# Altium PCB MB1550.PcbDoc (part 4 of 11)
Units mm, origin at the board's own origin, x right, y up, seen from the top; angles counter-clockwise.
Board outline 154.81 x 170.69 mm, 6 copper layers (Top Layer, Signal Layer 1, Signal Layer 2, Signal Layer 3, Signal Layer 4, Bottom Layer), stack 1.49 mm thick; 810 components, 633 nets, 2973 pads, 2150 vias.
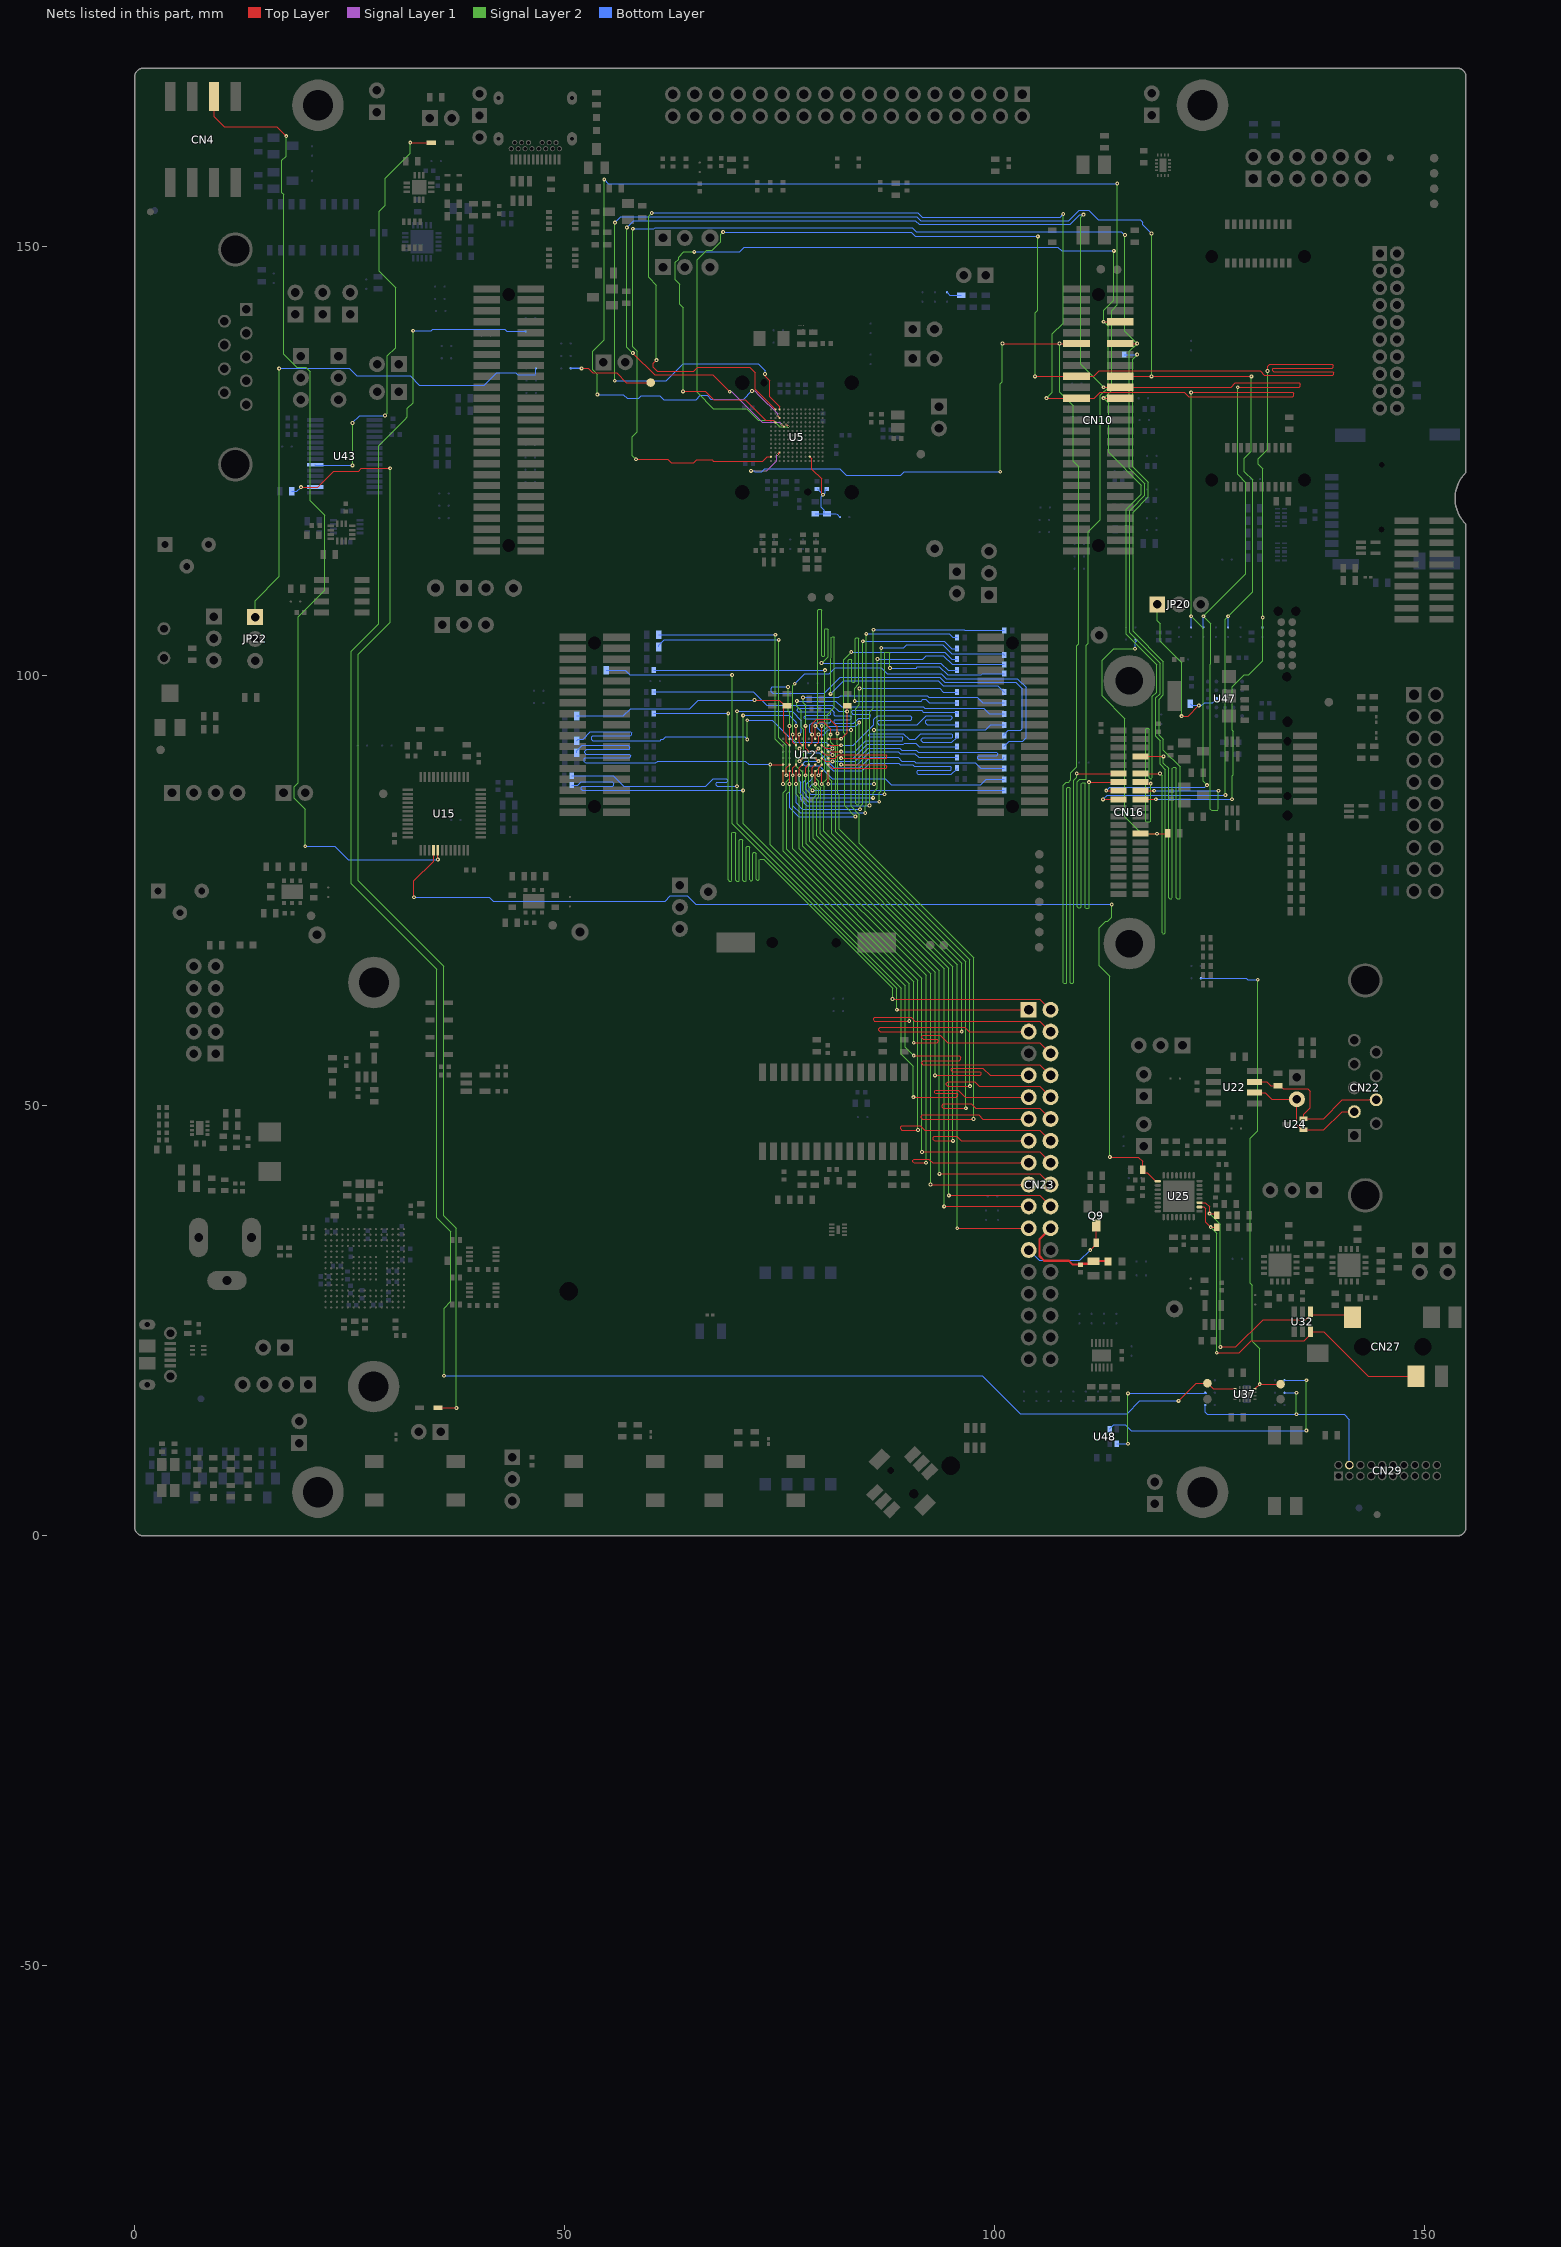
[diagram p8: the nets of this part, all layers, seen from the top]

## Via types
v1: diameter 0.45, hole 0.2, Top Layer to Bottom Layer, tented both sides, 1777 vias
v2: diameter 0.25, hole 0.1, Top Layer to Signal Layer 1, tented top, 344 vias
v3: diameter 0.25, hole 0.1, Signal Layer 1 to Signal Layer 2, 29 vias

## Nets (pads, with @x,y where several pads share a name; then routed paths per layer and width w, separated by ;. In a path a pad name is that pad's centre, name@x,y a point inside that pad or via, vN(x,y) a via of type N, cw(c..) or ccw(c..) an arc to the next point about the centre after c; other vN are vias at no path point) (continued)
A7: R221.2 U12.D4 | length 29.6
  Top Layer w0.1: v1(77.3,91.546) U12.D4@77.65,91.196
  Bottom Layer w0.1: v1(77.3,91.546) 77.771,91.075 79.625,91.075 80.375,90.325 80.375,89.85 81.229,88.996 84.611,88.996 85.49,89.875 88.853,89.875 89.033,89.694 90.456,89.694 90.65,89.5 94.825,89.5 94.95,89.375 94.95,89.075 94.9,89.025 91.075,89.025 90.975,88.925 90.975,88.675 91.075,88.575 94.975,88.575 95.625,89.225 R221.2@95.625,89.275
A8: R219.2 U12.H2 | length 26.9
  Top Layer w0.1: U12.H2@80.65,89.696 81.096,89.25 87.35,89.25 87.45,89.35 87.45,89.525 87.279,89.696 v1(82.146,89.696)
  Bottom Layer w0.1: v1(82.146,89.696) 83.996,89.696 85.475,91.175 88.8,91.175 89.011,90.964 90.711,90.964 91.15,90.525 R219.2@95.625,90.525
A9: R215.2 U12.H3 | length 26.9
  Top Layer w0.1: U12.H3@80.65,90.446 81.446,90.446 81.825,90.825 87.375,90.825 87.45,90.75 87.45,90.517 87.379,90.446 v1(82.146,90.446)
  Bottom Layer w0.1: v1(82.146,90.446) 83.546,90.446 85.175,92.075 89.4,92.075 89.523,92.198 90.827,92.198 91.25,91.775 R215.2@95.625,91.775
A10: R209.2 U12.H4 | length 32.9
  Top Layer w0.1: U12.H4@80.65,91.196 v1(82.146,91.196)
  Bottom Layer w0.1: v1(82.146,91.196) 83.706,91.196 85.002,92.492 89.227,92.492 89.325,92.59 89.325,92.85 89.25,92.925 85.5,92.925 85.375,93.05 85.375,93.185 85.498,93.308 89.392,93.308 90.049,92.651 90.775,92.651 91.432,93.308 94.992,93.308 95.1,93.2 95.1,92.9 95.025,92.825 91.625,92.825 91.45,92.65 91.45,92.475 91.625,92.3 95.025,92.3 95.625,92.9 R209.2@95.625,93.05
A11: R203.2 U12.H5 | length 32.6
  Top Layer w0.1: U12.H5@80.65,91.946 v1(82.146,91.946)
  Bottom Layer w0.1: v1(82.146,91.946) 83.546,91.946 85.95,94.35 85.95,94.95 86.4,95.4 90.175,95.4 90.35,95.225 90.35,94.975 90.225,94.85 86.55,94.85 86.4,94.7 86.4,94.475 86.525,94.35 91.025,94.35 92.066,95.391 94.884,95.391 95.05,95.225 95.05,95.063 94.912,94.925 92.1,94.925 91.975,94.8 91.975,94.517 92.142,94.35 R203.2@95.625,94.35
A12: R217.2 U12.G3 | length 27.5
  Top Layer w0.1: U12.G3@79.9,90.446 80.275,90.071 v1(81.146,90.071)
  Bottom Layer w0.1: v1(81.146,90.071) 83.782,90.071 85.302,91.592 88.973,91.592 89.183,91.381 90.883,91.381 91.115,91.15 100.203,91.15 100.35,91.003 100.35,90.825 100.25,90.725 98.15,90.725 98.025,90.6 98.025,90.4 98.1,90.325 100.925,90.325 R217.2@101.125,90.525
A13: R222.2 U12.G4 | length 26.9
  Top Layer w0.1: U12.G4@79.9,91.196 80.275,90.821 v1(81.146,90.821)
  Bottom Layer w0.1: v1(81.146,90.821) 80.142,91.825 80,91.825 79.878,91.703 79.878,91.297 80.75,90.425 80.75,89.925 81.375,89.3 84.325,89.3 85.55,90.525 88.792,90.525 89.206,90.111 90.628,90.111 90.815,89.925 97.716,89.925 98.391,89.25 R222.2@101.125,89.25
A14: R226.2 U12.F3 | length 27.1
  Top Layer w0.1: U12.F3@79.15,90.446 v1(79.5,90.096)
  Bottom Layer w0.1: v1(79.5,90.096) 77.971,90.096 77.8,89.925 77.8,89.7 77.95,89.55 79.625,89.55 81.14,88.035 87.265,88.035 87.975,87.325 98.375,87.325 99.025,87.975 R226.2@101.125,87.975
A15: R229.2 U12.F4 | length 28.3
  Top Layer w0.1: U12.F4@79.15,91.196 v1(79.5,91.546)
  Signal Layer 2 w0.09: v1(78.825,86.7) 78.4,87.125 78.4,90.446 v1(79.5,91.546)
  Bottom Layer w0.1: v1(78.825,86.7) R229.2@101.125,86.7
A16: R196.1 U12.E4 | length 30.4
  Top Layer w0.1: v1(78.025,94.2) 78.025,91.571 U12.E4@78.4,91.196
  Signal Layer 2 w0.09: v1(77.725,97.5) 77.725,96.9 78.025,96.6 v1(78.025,94.2)
  Bottom Layer w0.1: v1(77.725,97.5) 81.879,97.5 82.075,97.695 92.167,97.695 92.362,97.5 97.975,97.5 98.6,96.875 R196.1@101.125,96.875
A17: R199.1 U12.D3 | length 32.8
  Top Layer w0.1: v1(77.3,90.096) U12.D3@77.65,90.446
  Signal Layer 2 w0.09: v1(77,97.083) 77,96.475 77.525,95.95 77.525,94.025 77.8,93.75 77.8,90.596 v1(77.3,90.096)
  Bottom Layer w0.1: v1(77,97.083) 81.542,97.083 82.2,96.425 91.692,96.425 91.892,96.225 98.729,96.225 99.354,95.6 R199.1@101.125,95.6
A18: R204.1 U12.H1 | length 28.5
  Top Layer w0.1: v1(80.65,87.45) U12.H1@80.65,88.946
  Signal Layer 2 w0.09: v1(85.975,87.45) v1(85.975,93.725)
  Bottom Layer w0.1: v1(80.65,87.45) v1(85.975,87.45) ; v1(85.975,93.725) 98.975,93.725 99.575,94.325 R204.1@101.125,94.325
A19: R189.1 U12.G2 | length 33.8
  Top Layer w0.1: v1(79.525,88.45) 79.525,89.321 U12.G2@79.9,89.696
  Signal Layer 2 w0.09: v1(79.525,88.45) 80.266,89.191 80.266,94.975 80.265,94.976 v1(80.265,100.675)
  Bottom Layer w0.1: R189.1@60.375,100.675 v1(80.265,100.675)
A20: R38.1 R191.2 U12.H6 | length 29
  Top Layer w0.1: U12.H6@80.65,92.696 v1(82.146,92.696) 82.85,93.4 v1(82.85,95.875) R38.1@82.85,96.525
  Bottom Layer w0.1: R191.2@60.375,98.15 71.95,98.15 73.5,96.6 81.125,96.6 81.85,95.875 v1(82.85,95.875)
ADC_DAC: R144.2 SB16.2 | length 1.8
  Bottom Layer w0.12: SB16.2@94.475,144.625 94.8,144.3 R144.2@96.1,144.3
ADF1_CCK0: SB115.2 TP36.1 U37.16 | length 57.8
  Top Layer w0.12: U37.16@130.275,17.1 v1(130.825,17.65) TP36.1@133.25,17.65
  Signal Layer 2 w0.12: v1(130.6,64.675) 130.6,47.1 129.72,46.22 129.72,29.405 129.975,29.15 129.975,22.625 130.825,21.775 v1(130.825,17.65)
  Bottom Layer w0.12: SB115.2@123.975,64.85 123.975,64.82 129.282,64.82 129.427,64.675 v1(130.6,64.675)
ADF1_CCK0_MEMS: SB134.2 U48.4 | length 31.8
  Signal Layer 2 w0.12: v1(136.245,12.245) v1(136.245,18.095)
  Bottom Layer w0.12: U48.4@113.367,12.388 113.367,12.444 113.854,12.93 115.195,12.93 115.88,12.245 v1(136.245,12.245) ; SB134.2@133.7,18.1 v1@136.25,18.1
ADF1_SDIN0: SB26.2 TP35.1 U37.5 | length 238.4
  Top Layer w0.12: v1(121.4,15.7) 123.45,17.75 TP35.1@124.75,17.75 125.4,17.1 U37.5@127.925,17.1
  Signal Layer 2 w0.12: v1(32.375,140.15) 32.375,131.768 31.72,131.113 31.72,130.12 31.475,129.875 28.395,126.795 28.395,106.07 25.2,102.875 25.2,75.85 35.15,65.9 35.15,36.975 36.755,35.37 36.755,27.28 35.975,26.5 v1(35.975,18.625)
  Bottom Layer w0.12: v1(32.375,140.15) 34.475,140.15 34.655,140.33 43.018,140.33 43.273,140.075 SB26.2@45.45,140.075 ; v1(35.975,18.625) 98.575,18.625 103.005,14.195 115.395,14.195 116.9,15.7 v1(121.4,15.7)
ADF1_SDIN0_MEMS: SB145.2 U48.1 | length 16.3
  Signal Layer 2 w0.12: v1(115.5,10.712) v1(115.5,16.575)
  Bottom Layer w0.12: U48.1@114.189,10.712 v1(115.5,10.712) ; v1(115.5,16.575) 124.65,16.575
AGND: C140.1 C141.1 C148.2 C149.2 SB76.2 U5.K2 | length 12.4
  Top Layer w0.08: U5.K2@78.5,125.5 78.75,125.25 78.75,124.05 79.875,122.925 79.875,121.25 v1(80.05,121.075)
  Bottom Layer w0.1: C149.2@79.125,118.875 C148.2@80.2,118.875 ; C141.1@79.35,121.75 79.375,121.75 v1(80.05,121.075) ; C140.1@80.475,121.75 80.3,121.575 80.3,121.325 v1(80.05,121.075) ; 81.675,118.8 81.6,118.875 C148.2@80.5,118.875 C148.2@80.2,118.875 ; v1(80.05,121.075) 79.825,120.85 79.825,119.625 80.2,119.25 C148.2@80.2,118.875
  Bottom Layer w0.12: 81.675,118.8 SB76.2@82,118.475
AOUTA: C84.2 CN27.6 U25.11 U32.4 | length 36.4
  Top Layer w0.12: U25.11@123.825,38.75 124.5,38.75 125,38.25 v1(125,37.475) 125.625,37.475 C84.2@125.8,37.3 ; v1(126.25,21.975) 128.05,21.975 131.225,25.15 136.2,25.15 136.75,25.7 U32.4@136.75,25.725 ; U32.4@136.75,26.05 U32.4@136.75,25.725 ; CN27.6@141.6,25.45 141.325,25.725 U32.4@136.75,25.725
  Signal Layer 2 w0.12: v1(125,37.475) 126.25,36.225 v1(126.25,21.975)
AOUTB: C86.2 CN27.4 U25.10 U32.3 | length 45.3
  Top Layer w0.12: U25.10@123.825,38.25 124.325,38.25 124.55,38.025 124.55,36.475 v1(125.125,35.9) C86.2@125.8,35.9 ; v1(125.825,21.3) 128.425,21.3 129.825,22.7 136,22.7 136.75,23.45 U32.3@136.75,23.75 138.275,23.75 143.475,18.55 CN27.4@149,18.55
  Signal Layer 2 w0.12: v1(125.125,35.9) 125.825,35.2 v1(125.825,21.3)
BL_CTRL: CN23.23 Q9.3 R104.1 | length 11.3
  Top Layer w0.12: v1(111.125,33.225) 111.8,33.9 R104.1@111.8,34.1 Q9.3@111.8,36.1
  Bottom Layer w0.12: CN23.23@103.96,33.24 105.175,32.025 109.925,32.025 v1(111.125,33.225)
BLGND: C92.1 C93.1 CN23.22 L3.2 | length 12.3
  Top Layer w0.25: CN23.22@106.5,35.78 105.225,34.505 105.225,32.55 105.775,32 108.625,32 109.075,31.55 C93.1@110,31.55 110.1,31.65 111.2,31.65 C92.1@111.5,31.95 113.15,31.95 L3.2@113.2,31.9
Bootloader_BOOT0: D1.1 U43.20 | length 50.5
  Top Layer w0.12: v1(32.04,162.025) D1.1@34.48,162.025
  Signal Layer 2 w0.12: v1(25.325,124.49) v1(25.325,129.425) ; v1(29.1,130.286) 29.375,130.561 29.375,137.222 30.338,138.185 30.338,145.144 28.425,147.057 28.425,154.05 29.125,154.75 29.125,157.9 32.04,160.815 v1(32.04,162.025)
  Bottom Layer w0.12: U43.20@20.976,124.561 20.976,124.495 20.981,124.49 v1(25.325,124.49) ; v1(25.325,129.425) 25.3,129.425 26.161,130.286 v1(29.1,130.286)
BOOTLOADER_RST: D9.2 R161.2 U43.16 | length 131.9
  Top Layer w0.12: v1(19.336,121.961) 21.286,121.961 23.151,123.825 26.025,123.825 26.35,124.15 v1(29.7,124.15) ; D9.2@35.27,14.9 35.5,14.9 35.525,14.875 v1(37.4,14.875)
  Signal Layer 2 w0.12: v1(29.7,124.15) 29.7,106.225 26,102.525 26,76.175 35.95,66.225 35.95,37.225 37.4,35.775 v1(37.4,14.875)
  Bottom Layer w0.12: R161.2@18.25,121.475 18.85,121.475 v1(19.336,121.961) U43.16@20.976,121.961
CAMERA_PLUG: CN16.15 R52.1 SB103.2 | length 32.6
  Top Layer w0.12: CN16.15@116.95,81.655 v1(118.87,81.655) 120.055,81.655 R52.1@120.125,81.725
  Signal Layer 2 w0.12: v1(116.325,103.163) 113.838,103.163 112.495,101.82 112.495,97.705 115.15,95.05 115.15,83.625 117.12,81.655 v1(118.87,81.655)
  Bottom Layer w0.12: v1(116.325,103.163) 116.325,103.925 116.625,104.225
CANH: CN22.7 R81.1 U22.7 U24.2 | length 19.8
  Top Layer w0.12: U24.2@135.925,48.525 138.25,48.525 140.44,50.715 CN22.7@144.37,50.715
  Top Layer w0.13: U22.7@130.225,52.81 131.665,52.81 132.1,52.375 R81.1@132.95,52.375 133.175,52.375 133.55,52 136.4,52 136.7,51.7 136.7,49.785 135.925,49.01 U24.2@135.925,48.525
CANL: CN22.2 JP28.2 U22.6 U24.1 | length 16
  Top Layer w0.12: U24.1@135.925,47.225 138.3,47.225 140.405,49.33 CN22.2@141.83,49.33
  Top Layer w0.13: U22.6@130.225,51.54 131.485,51.54 132.25,50.775 JP28.2@135.15,50.775 135.15,47.8 135.725,47.225 U24.1@135.925,47.225
CCK0_EXT: CN29.4 SB144.2 SB147.2 | length 27.1
  Signal Layer 2 w0.12: v1(135.1,14.15) v1(135.1,16.65)
  Bottom Layer w0.12: SB147.2@124.5,15.225 124.5,14.4 124.75,14.15 v1(135.1,14.15) 140.631,14.15 141.255,13.526 CN29.4@141.255,8.235 ; SB144.2@133.7,16.65 v1(135.1,16.65)
CODEC_RSTN: R85.2 U15.28 U25.25 | length 126.6
  Top Layer w0.12: v1(32.475,74.275) 32.475,76.2 34.748,78.473 U15.28@34.748,79.75 ; v1(113.4,44.05) 116.7,44.05 117.2,43.55 R85.2@117.2,42.6 117.2,42.225 117.775,42.225 118.75,41.25 U25.25@118.975,41.25
  Signal Layer 2 w0.12: v1(113.4,44.05) 113.4,65.1 112.175,66.325 112.175,70.733 112.916,71.474 113.141,71.474 113.625,71.958 v1(113.625,73.425)
  Bottom Layer w0.12: v1(32.475,74.275) 41.2,74.275 41.675,73.8 61.675,73.8 62.3,74.425 64.25,74.425 65.25,73.425 v1(113.625,73.425)
COMP2_INP: JP22.1 SB40.2 | length 62.1
  Signal Layer 2 w0.12: JP22.1@14,106.84 14,108.775 16.795,111.57 v1(16.795,135.765)
  Bottom Layer w0.12: v1(16.795,135.765) 24.96,135.765 25.81,134.915 32.035,134.915 33.115,133.835 40.635,133.835 42.075,135.275 44.333,135.275 44.558,135.05 46.55,135.05 46.65,135.15 SB40.2@46.65,135.775
COMP2_OUT: SB39.2 TP9.1 | length 10
  Top Layer w0.102: v1(51.975,135.775) 52.725,135.775 53.25,135.25 56.05,135.25
  Top Layer w0.12: 56.05,135.25 57.175,134.125 TP9.1@60,134.125
  Bottom Layer w0.2: SB39.2@50.7,135.775 v1(51.975,135.775)
CSn: JP20.1 R195.1 U47.C2 | length 20.1
  Top Layer w0.12: v1(121.75,95.325) 122.5,95.325 v1(123.75,96.575)
  Signal Layer 2 w0.12: JP20.1@118.91,108.325 118.91,106.44 119.25,106.1 119.25,104.025 121.75,101.525 v1(121.75,95.325)
  Bottom Layer w0.12: R195.1@122.734,96.771 122.929,96.575 v1(123.75,96.575) 124.1,96.575 124.425,96.9 125.338,96.9 U47.C2@125.784,97.346
D0: CN23.6 R207.1 U12.B6 | length 110.9
  Top Layer w0.1: U12.B6@76.15,92.696 v1(76.15,94.192) ; v1(90.6,57.35) 93.325,57.35 93.425,57.45 93.425,57.625 93.3,57.75 91.7,57.75 91.55,57.9 91.55,58.075 91.7,58.225 93.675,58.225 94.55,57.35 105.25,57.35 CN23.6@106.5,56.1
  Signal Layer 2 w0.09: v1(75.975,98.725) 75.975,95.9 76.15,95.725 v1(76.15,94.192) 76.15,88.1 75.765,87.715 75.765,87.284 75.75,87.269 75.75,86.75 75.425,86.425 75.425,79.6 90.6,64.425 v1(90.6,57.35)
  Bottom Layer w0.1: v1(75.975,98.725) 74.125,98.725 74,98.6 74,98.15 74.167,97.983 80.2,97.983 82.071,99.854 93.631,99.854 94.202,99.283 102.467,99.283 103.225,98.525 103.225,93.875 103.025,93.675 101.575,93.675 101.125,93.225 R207.1@101.125,93.075
D1: CN23.7 R213.1 U12.C5 | length 110.2
  Top Layer w0.1: v1(76.525,93.192) 76.525,92.321 U12.C5@76.9,91.946 ; v1(93.075,53.56) 98.325,53.56 98.425,53.66 98.425,53.9 98.325,54 95.075,54 94.925,54.15 94.925,54.3 95.008,54.383 98.642,54.383 99.465,53.56 CN23.7@103.96,53.56
  Signal Layer 2 w0.09: v1(76.75,99.1) 76.534,98.884 76.534,93.201 v1(76.525,93.192) 76.525,92.675 76.935,92.265 76.935,89.515 77.66,88.79 77.66,86.64 78.1,86.2 78.1,80.5 93.075,65.525 v1(93.075,53.56)
  Bottom Layer w0.1: v1(76.75,99.1) 77.908,100.258 80.748,100.258 81.439,100.949 86.832,100.949 87.51,100.271 93.804,100.271 94.375,99.7 102.64,99.7 103.675,98.665 103.675,92.825 103.275,92.425 101.7,92.425 101.125,91.85 R213.1@101.125,91.8
D2: CN23.8 R228.1 U12.C6 | length 110.7
  Top Layer w0.1: U12.C6@76.9,92.696 v1(76.9,94.192) ; v1(90.6,55.85) 95.875,55.85 96.075,55.65 96.075,55.45 95.9,55.275 91.7,55.275 91.5,55.075 91.5,54.95 91.65,54.8 105.26,54.8 CN23.8@106.5,53.56
  Signal Layer 2 w0.09: v1(70.75,95.425) v1(70.75,86.7) 70.75,82.825 89.625,63.95 89.625,56.825 v1(90.6,55.85)
  Bottom Layer w0.1: R228.1@50.834,87.296 51.521,87.296 51.9,87.675 55.525,87.675 55.729,87.471 55.729,87.296 55.583,87.15 52.05,87.15 51.95,87.05 51.95,86.801 52.051,86.7 v1(70.75,86.7) ; v1(70.75,95.425) 76.1,95.425 76.9,94.625 v1(76.9,94.192)
D3: CN23.9 R224.1 U12.D5 | length 107.5
  Top Layer w0.1: v1(77.275,93.192) 77.275,92.321 U12.D5@77.65,91.946 ; v1(90.55,51.02) 95.55,51.02 95.725,51.195 95.725,51.3 95.575,51.45 93.125,51.45 93.025,51.55 93.025,51.75 93.125,51.85 95.745,51.85 96.575,51.02 CN23.9@103.96,51.02
  Signal Layer 2 w0.09: v1(70.05,95.9) v1(70.05,87.175) 70.05,82.8 89.15,63.7 89.15,56.025 90.55,54.625 v1(90.55,51.02)
  Bottom Layer w0.1: R224.1@50.834,88.396 55.629,88.396 56.85,87.175 66.4,87.175 67.258,88.033 68.817,88.033 68.975,87.875 68.975,87.75 68.875,87.65 67.7,87.65 67.6,87.55 67.6,87.3 67.725,87.175 v1(70.05,87.175) ; v1(70.05,95.9) 76.446,95.9 77.525,94.821 77.525,93.442 v1(77.275,93.192)
D4: CN23.10 R200.1 U12.E5 | length 114.2
  Top Layer w0.1: U12.E5@78.4,91.946 78.775,92.321 v1(78.775,93.192) 78.775,94.425 79.325,94.975 80.85,94.975 81.725,94.1 v1(81.725,93.325) ; v1(97.125,52.3) 94.575,52.3 94.4,52.475 94.4,52.625 94.6,52.825 97.675,52.825 98.2,52.3 105.22,52.3 CN23.10@106.5,51.02
  Signal Layer 2 w0.09: v1(81.725,93.325) 81.725,92.056 81.781,92 81.781,86.369 81.925,86.225 81.925,82.175 97.125,66.975 v1(97.125,52.3)
  Bottom Layer w0.1: v1(78.775,93.192) 78.525,93.442 78.525,94.325 78.775,94.575 80.825,94.575 80.925,94.675 80.925,94.875 80.8,95 77.975,95 77.875,95.1 77.875,95.275 78.025,95.425 80.775,95.425 80.925,95.575 80.925,95.7 80.775,95.85 77.15,95.85 77.05,95.95 77.05,96.1 77.175,96.225 80.875,96.225 81.325,95.775 81.325,95.45 81.404,95.371 83.2,95.371 83.3,95.271 83.3,95 83.2,94.9 81.425,94.9 81.325,94.8 81.325,94.6 81.4,94.525 83.6,94.525 84.175,95.1 85.375,95.1 85.55,95.275 85.55,95.45 85.45,95.55 83.525,95.55 83.375,95.7 83.375,95.875 83.508,96.008 91.519,96.008 91.72,95.808 95.625,95.808 R200.1@95.625,95.6
D5: CN23.11 R197.1 U12.F5 | length 112.5
  Top Layer w0.1: U12.F5@79.15,91.946 79.525,92.321 v1(79.525,93.192) ; v1(97.55,48.48) 91.57,48.48 91.45,48.6 91.45,48.825 91.575,48.95 98.175,48.95 98.645,48.48 CN23.11@103.96,48.48
  Signal Layer 2 w0.09: v1(83.725,97.083) 83.725,98.575 84.225,99.075 84.225,104.325 84.1,104.45 83.925,104.45 83.8,104.325 83.8,99.375 83.7,99.275 83.475,99.275 83.4,99.35 83.4,101.85 83.3,101.95 83.1,101.95 83,101.85 83,96.725 83.3,96.425 v1(83.3,93.725) 83.3,84.825 84.275,83.85 84.275,80.525 97.55,67.25 v1(97.55,48.48)
  Bottom Layer w0.1: v1(79.525,93.192) 80.142,93.192 80.675,93.725 v1(83.3,93.725) ; v1(83.725,97.083) 91.46,97.083 91.656,97.278 91.994,97.278 92.398,96.875 R197.1@95.625,96.875
D6: CN23.12 R193.1 U12.F6 | length 111.6
  Top Layer w0.1: U12.F6@79.15,92.696 v1(79.15,94.192) 79.633,94.675 80.05,94.675 80.925,93.8 v1(80.925,93.175) ; v1(96.65,49.725) 94.025,49.725 93.925,49.825 93.925,50.1 94.05,50.225 97.275,50.225 97.775,49.725 105.255,49.725 CN23.12@106.5,48.48
  Signal Layer 2 w0.09: v1(80.925,93.175) 80.925,92.308 81.511,91.722 81.511,91.42 81.511,81.889 96.65,66.75 v1(96.65,49.725) ; v1(84.25,94.575) 84.25,85.125 84.175,85.05 83.9,85.05 83.825,85.125 83.825,96.175 84.275,96.625 v1(84.275,98.548)
  Bottom Layer w0.1: v1(79.15,94.192) 79.717,93.625 80.05,93.625 80.575,94.15 83.85,94.15 84.25,94.55 v1(84.25,94.575) ; v1(84.275,98.548) 93.602,98.548 94.025,98.125 R193.1@95.625,98.125
D7: CN23.13 R188.1 U12.G6 | length 114.4
  Top Layer w0.1: U12.G6@79.9,92.696 v1(79.9,94.192) ; v1(95.15,45.94) 93.01,45.94 92.875,46.075 92.875,46.375 92.975,46.475 95.575,46.475 96.11,45.94 CN23.13@103.96,45.94
  Signal Layer 2 w0.09: v1(79.869,101.505) 80.625,102.262 80.625,105.4 80.55,105.475 80.325,105.475 80.225,105.375 80.225,102.375 80.125,102.275 79.969,102.275 79.869,102.375 79.869,107.631 79.75,107.75 79.55,107.75 79.45,107.65 79.45,94.642 v1(79.9,94.192) 79.9,89.625 79.16,88.885 79.16,88.14 79.535,87.765 79.535,87.24 79.8,86.975 79.8,85.7 79.7,85.6 79.7,83.475 79.692,83.467 79.692,81.658 95.15,66.2 v1(95.15,45.94)
  Bottom Layer w0.1: v1(79.869,101.505) 93.749,101.505 94.579,100.675 R188.1@95.625,100.675
D8: CN23.14 R185.1 U12.B1 | length 112.2
  Top Layer w0.1: v1(76.15,87.45) U12.B1@76.15,88.946 ; v1(91.075,47.2) 89.2,47.2 89.075,47.325 89.075,47.575 89.175,47.675 91.375,47.675 91.85,47.2 105.24,47.2 CN23.14@106.5,45.94
  Signal Layer 2 w0.09: v1(76.15,87.45) 76.15,86.6 75.825,86.275 75.825,79.875 91.075,64.625 v1(91.075,47.2) ; v1(83.325,102.775) 82.45,101.9 82.45,93.4 82.55,93.3 82.55,84.9 v1(83.8,83.65)
  Bottom Layer w0.1: v1(76.15,87.45) 76.15,84.7 77.2,83.65 v1(83.8,83.65) ; v1(83.325,102.775) 94.214,102.775 95.04,101.95 R185.1@95.625,101.95
D9: CN23.15 R182.1 U12.C1 | length 108.2
  Top Layer w0.1: v1(76.9,87.45) U12.C1@76.9,88.946 ; v1(92.025,43.4) 90.625,43.4 90.5,43.525 90.5,43.675 90.65,43.825 92.35,43.825 92.775,43.4 CN23.15@103.96,43.4
  Signal Layer 2 w0.09: v1(76.9,87.45) 76.9,86.225 77.3,85.825 77.3,79.9 92.025,65.175 v1(92.025,43.4) ; v1(84.35,84.508) 84.35,84.85 84.666,85.166 84.666,96.15 84.671,96.155 v1(84.671,104.045)
  Bottom Layer w0.1: v1(76.9,87.45) 76.9,85.25 77.642,84.508 v1(84.35,84.508) ; v1(84.671,104.045) 94.124,104.045 94.994,103.175 R182.1@95.625,103.175
D10: CN23.16 R180.1 U12.C2 | length 110.8
  Top Layer w0.1: v1(76.525,88.45) 76.525,89.321 U12.C2@76.9,89.696 ; v1(91.55,44.65) 105.25,44.65 CN23.16@106.5,43.4
  Signal Layer 2 w0.09: v1(76.525,88.45) 76.525,79.9 91.55,64.875 v1(91.55,44.65) ; v1(84.95,84.075) 84.95,84.885 85.054,84.989 85.054,85.089 85.058,85.093 85.058,95.987 85.075,96.004 v1(85.075,104.898)
  Bottom Layer w0.1: v1(76.525,88.45) 76.525,84.925 77.375,84.075 v1(84.95,84.075) ; v1(85.075,104.898) 94.702,104.898 95.1,104.5 R180.1@95.625,104.5
D11: CN23.17 R175.1 U12.D2 | length 113.8
  Top Layer w0.1: v1(77.275,88.45) 77.275,89.321 U12.D2@77.65,89.696 ; v1(92.55,40.86) CN23.17@103.96,40.86
  Signal Layer 2 w0.09: v1(77.275,88.45) 77.275,86.425 77.7,86 77.7,80.2 92.55,65.35 v1(92.55,40.86) ; v1(85.45,84.925) 85.45,95.825 85.9,96.275 v1(85.9,105.375)
  Bottom Layer w0.1: v1(77.275,88.45) 77.275,87.8 77.425,87.65 77.425,85.675 78.175,84.925 v1(85.45,84.925) ; v1(85.9,105.375) 96.475,105.375 96.55,105.3 R175.1@101.125,105.3
D12: CN23.18 R183.1 U12.E2 | length 112.3
  Top Layer w0.1: v1(78.025,88.45) 78.025,89.321 U12.E2@78.4,89.696 ; v1(93.575,42.1) 105.26,42.1 CN23.18@106.5,40.86
  Signal Layer 2 w0.09: v1(78.025,88.45) 78.025,86.85 78.492,86.383 78.492,80.783 93.575,65.7 v1(93.575,42.1) ; v1(86.575,85.375) 86.575,86.425 86.808,86.658 v1(86.808,103.258)
  Bottom Layer w0.1: v1(78.025,88.45) 78.025,87.925 77.75,87.65 77.75,85.95 78.325,85.375 v1(86.575,85.375) ; v1(86.808,103.258) 89.43,103.258 89.8,103.628 93.951,103.628 95.004,102.575 100.975,102.575 R183.1@101.125,102.425
D13: CN23.19 R186.1 U12.F2 | length 110.2
  Top Layer w0.1: v1(78.775,88.45) 78.775,89.321 U12.F2@79.15,89.696 ; v1(94.125,38.32) CN23.19@103.96,38.32
  Signal Layer 2 w0.09: v1(78.775,88.45) 78.775,87.275 79.25,86.8 79.25,86.125 78.9,85.775 78.9,81.15 94.125,65.925 v1(94.125,38.32) ; v1(85.875,85.825) 85.875,86.425 86.371,86.921 v1(86.371,101.971)
  Bottom Layer w0.1: v1(78.775,88.45) 78.775,88.075 78.1,87.4 78.1,86.075 78.35,85.825 v1(85.875,85.825) ; v1(86.371,101.971) 91.638,101.971 92.025,102.358 94.042,102.358 95.05,101.35 R186.1@101.125,101.35
D14: CN23.20 R190.1 U12.F1 | length 111.3
  Top Layer w0.1: v1(79.15,87.45) U12.F1@79.15,88.946 ; v1(94.675,39.6) 105.22,39.6 CN23.20@106.5,38.32
  Signal Layer 2 w0.09: v1(79.15,87.45) 79.15,87.2 79.55,86.8 79.55,85.95 79.3,85.7 79.3,81.4 94.675,66.025 v1(94.675,39.6) ; v1(87.2,86.25) 87.2,102.675 87.3,102.775 87.675,102.775 87.825,102.625 v1(87.825,100.925)
  Bottom Layer w0.1: v1(79.15,87.45) 78.875,87.45 78.447,87.022 78.447,86.425 78.621,86.25 v1(87.2,86.25) ; v1(87.825,100.925) 90.862,100.925 91.025,101.088 93.576,101.088 94.548,100.117 98.442,100.117 98.6,100.275 R190.1@101.125,100.275
D15: CN23.21 R192.1 U12.G1 | length 114.1
  Top Layer w0.1: v1(79.9,87.45) U12.G1@79.9,88.946 ; v1(95.65,35.78) CN23.21@103.96,35.78
  Signal Layer 2 w0.09: v1(80.925,97.925) 80.925,102.007 81.017,102.099 81.017,104.475 81.117,104.575 81.275,104.575 81.375,104.475 81.375,96.35 80.525,95.5 80.525,88.075 v1(79.9,87.45) 80.2,87.15 80.2,85.525 80.125,85.45 80.125,81.95 95.65,66.425 v1(95.65,35.78)
  Bottom Layer w0.1: v1(80.925,97.925) 82.437,99.437 93.458,99.437 94.03,98.866 100.384,98.866 R192.1@101.125,98.125
DCMI_D0: CN10.17 CN16.23 SB95.1 U5.E9 | length 209.3
  Top Layer w0.08: v2(75.75,129.25) v3(76,129)
  Top Layer w0.1: v1(104.704,134.845) CN10.17@109.523,134.845 111.545,134.845 112.175,135.475 130.875,135.475 131.375,134.975 139.325,134.975 139.425,135.075 139.425,135.275 139.3,135.4 132.45,135.4 132.35,135.5 132.35,135.725 132.425,135.8 139.275,135.8 139.4,135.925 139.4,136.15 139.275,136.275 132.002,136.275 131.731,136.004 v1(131.731,135.475) ; CN16.23@116.955,85.66 v1(118.75,85.66)
  Signal Layer 1 w0.08: v2(75.75,129.25) v3(76,129)
  Signal Layer 2 w0.09: v1(68.425,151.625) 68.153,151.353 68.153,150.503 67.175,149.525 66.525,149.525 65.398,148.398 65.398,132.977 67.275,131.1 71.15,131.1 72.5,129.75 74.25,129.75 75,129 v3(76,129) ; v1(104.704,134.845) 104.704,142.22 105.025,142.541 v1(105.025,151.12) ; v1(127.614,85.66) 127.614,88.39 127.75,88.527 127.75,93.539 127.614,93.675 127.614,98.736 129.024,100.146 129.546,100.146 131.182,101.782 v1(131.182,106.807) 131.182,124.1 130.654,124.628 130.654,125.279 131.731,126.356 v1(131.731,135.475)
  Bottom Layer w0.1: v1(68.425,151.625) 90.275,151.625 90.78,151.12 v1(105.025,151.12) ; v1(118.75,85.66) v1(127.614,85.66) ; 131.182,105.506 131.182,105.65 v1(131.182,106.807)
DCMI_D1: CN10.18 CN16.24 SB97.1 U5.C13 | length 207
  Top Layer w0.1: v1(73.3,135.125) 73.3,134.875 73.825,134.35 73.825,132.475 75,131.3 U5.C13@75,131 ; v1(112.6,85.65) CN16.24@114.395,85.65 ; CN10.18@114.623,134.845 v1(118.25,134.845) v1(129.854,134.845)
  Top Layer w0.127: CN16.24@114.395,85.65 CN16.24@114.4,85.655
  Signal Layer 2 w0.09: v1(55.825,134.325) 55.846,134.346 v1(55.846,152.721) ; v1(118.25,134.845) v1(118.25,151.45) ; v1(126.825,86.15) 126.822,86.153 126.822,106.623 v1(127.15,106.951) 130.006,109.807 130.006,122.815 129.054,123.767 129.054,125.342 129.854,126.142 v1(129.854,134.845)
  Bottom Layer w0.1: v1(55.825,134.325) 61.835,134.325 63.81,136.3 72.5,136.3 73.3,135.5 v1(73.3,135.125) ; v1(55.846,152.721) 56.537,153.412 90.918,153.412 91.395,152.934 108.62,152.934 109.835,154.15 110.967,154.15 112.05,153.067 116.943,153.067 117.225,152.785 117.225,152.475 v1(118.25,151.45) ; v1(112.6,85.65) 113.1,86.15 v1(126.825,86.15) ; SB97.1@127.15,105.65 v1(127.15,106.951)
DCMI_D2: CN10.20 CN16.25 SB99.1 U5.D9 | length 207.6
  Top Layer w0.08: v2(75.25,129.25) U5.D9@75.5,129
  Top Layer w0.1: v1(57.925,137.55) 60.45,135.025 67.225,135.025 v1(69.2,133.05) ; v1(112.677,133.575) CN10.20@114.623,133.575 127.5,133.575 128,134.075 135.425,134.075 135.55,133.95 135.55,133.675 135.45,133.575 v1(128.27,133.575) ; CN16.25@116.95,86.655 v1(118.545,86.655)
  Signal Layer 1 w0.08: v1(69.2,133.05) 69.45,133.05 73,129.5 75,129.5 v2(75.25,129.25)
  Signal Layer 2 w0.09: v1(57.225,152.15) 57.225,138.25 v1(57.925,137.55) ; v1(110.325,153.65) 110.021,153.346 110.021,136.231 v1(112.677,133.575) ; v1(126.03,86.655) 126.03,84.48 125.95,84.4 125.225,84.4 125.096,84.529 125.096,101.346 125.144,101.394 125.144,106.082 v1(124.275,106.951) 129.222,111.898 129.222,122.49 128.27,123.442 v1(128.27,133.575)
  Bottom Layer w0.1: v1(57.225,152.15) 58.042,152.967 90.773,152.967 91.222,152.517 108.793,152.517 109.925,153.65 v1(110.325,153.65) ; v1(118.545,86.655) v1(126.03,86.655) ; SB99.1@124.275,105.65 v1(124.275,106.951)
DCMI_D3: CN10.21 CN16.26 SB100.1 U5.B13 | length 209.4
  Top Layer w0.1: v1(60.675,136.725) 60.325,136.375 60.325,135.916 60.783,135.458 65.008,135.458 65.45,135.9 71.525,135.9 72.151,135.274 72.151,133.349 U5.B13@74.5,131 ; v1(106.025,132.305) CN10.21@109.523,132.305 111.605,132.305 112.266,132.966 122.059,132.966 122.55,132.475 134.65,132.475 134.775,132.6 134.775,132.866 134.675,132.966 v1(122.85,132.966) ; v1@113.075,86.665 114.39,86.665 CN16.26@114.4,86.655
  Top Layer w0.127: v1(112.975,86.665) v1@113.075,86.665
  Signal Layer 2 w0.09: v1(60.125,153.85) 59.758,153.483 59.758,146.366 60.675,145.449 v1(60.675,136.725) ; v1(106.025,132.305) 106.725,133.005 106.725,139.775 107.978,141.028 v1(107.978,153.728) ; v1(122.85,132.966) v1(122.85,106.951) 124.241,105.56 124.241,87.759 v1(124.7,87.3)
  Bottom Layer w0.1: v1(60.125,153.85) 91.069,153.85 91.568,153.351 107.601,153.351 v1(107.978,153.728) ; v1(112.975,86.665) 113.371,87.061 118.373,87.061 118.376,87.063 118.759,87.063 118.781,87.041 124.441,87.041 v1(124.7,87.3) ; SB100.1@122.85,105.65 v1(122.85,106.951)
DCMI_D4: CN10.22 CN16.27 U5.C11 | length 209.1
  Top Layer w0.1: v2(74.75,130.25) U5.C11@75,130 ; v1(112.677,132.305) CN10.22@114.623,132.305 ; CN16.27@116.95,87.675 116.96,87.665 117.15,87.475 v1(118.15,87.475)
  Signal Layer 1 w0.08: v1(71.775,133.15) 72.075,133.15 72.575,132.65 74.75,130.475 v2(74.75,130.25)
  Signal Layer 2 w0.09: v1(53.8,132.725) 53.8,135.1 53.275,135.625 53.275,137.775 54.599,139.099 v1(54.599,157.749) ; v1(114.265,157.264) 114.265,143.165 113.597,142.497 113.597,133.225 v1(112.677,132.305) 113.25,131.732 113.25,126.021 117.075,122.196 117.075,121.15 115.767,119.842 115.308,119.383 115.308,104.858 118.846,101.32 118.846,98.111 118.354,97.62 118.354,88.154 118.25,88.05 118.1,88.05 117.975,88.175 117.975,93.825 117.875,93.925 117.695,93.925 117.575,93.805 117.575,83.125 117.675,83.025 118.05,83.025 118.15,83.125 v1(118.15,87.475)
  Bottom Layer w0.1: v1(53.8,132.725) 56.825,132.725 57.258,132.292 58.617,132.292 58.9,132.575 61.05,132.575 61.5,132.125 65.3,132.125 65.793,132.618 66.582,132.618 67,132.2 70.825,132.2 v1(71.775,133.15) ; v1(54.599,157.749) 55.084,157.264 56.382,157.264 56.386,157.26 90.339,157.26 90.343,157.264 v1(114.265,157.264)
DCMI_D5: CN10.8 CN16.28 U5.B10 | length 208.9
  Top Layer w0.08: 73.375,129.75 74.25,129.75 U5.B10@74.5,129.5
  Top Layer w0.1: v1(63.765,133.097) 66.353,133.097 67.337,132.113 71.012,132.113 73.375,129.75 ; v1(110.979,87.655) CN16.28@114.4,87.655 ; v1(112.675,141.195) CN10.8@114.623,141.195
  Signal Layer 2 w0.09: v1(63.765,133.097) 63.765,142.81 63.373,143.202 63.373,145.558 62.874,146.057 62.874,148.099 63.246,148.471 63.246,148.714 63.857,149.325 v1(65.066,149.325) ; v1(110.979,87.655) 110.979,73.054 110.9,72.975 110.625,72.975 110.525,73.075 110.525,87.5 110.45,87.575 110.225,87.575 110.1,87.45 110.1,73.15 109.975,73.025 109.725,73.025 109.6,73.15 109.6,87.7 109.9,88 110.654,88 110.654,103.577 110.859,103.782 110.859,116.759 112.276,118.176 112.276,132.632 112.823,133.179 112.841,133.179 113.205,133.543 113.205,140.665 v1(112.675,141.195) 112.675,142.525 113.864,143.715 v1(113.864,149.435)
  Bottom Layer w0.1: v1(65.066,149.325) 70.35,149.325 70.894,149.869 107.361,149.869 107.795,149.435 v1(113.864,149.435)
DCMI_D6: CN10.12 CN16.29 U5.A2 | length 210.4
  Top Layer w0.1: v1(58.3,125.2) 61.975,125.2 62.392,124.783 65.023,124.783 65.365,125.125 67.15,125.125 67.3,124.975 73.025,124.975 73.55,125.5 U5.A2@74,125.5 ; CN10.12@114.623,138.655 v1(116.569,138.655) ; CN16.29@116.95,88.655 v1(119.238,88.655)
  Signal Layer 2 w0.09: v1(57.929,152.004) 57.929,138.296 58.436,137.789 58.436,128.394 57.875,127.833 57.875,125.625 v1(58.3,125.2) ; v1(115.15,151.275) 115.15,140.074 v1(116.569,138.655) 115.65,137.736 115.65,124.175 117.467,122.358 117.467,120.988 115.93,119.45 115.7,119.221 115.7,105.021 119.238,101.483 119.238,97.949 118.746,97.457 118.746,92.967 119.238,92.475 119.238,89.712 119.85,89.1 119.85,70.15 119.75,70.05 119.55,70.05 119.475,70.125 119.475,88.418 v1(119.238,88.655)
  Bottom Layer w0.1: v1(57.929,152.004) 60.379,152.004 60.504,152.128 90.422,152.128 90.867,151.683 114.742,151.683 v1(115.15,151.275)
DCMI_D7: CN10.11 CN16.30 U5.C3 | length 209.9
  Top Layer w0.1: v2(74.75,125.75) U5.C3@75,126 ; v1(100.904,138.655) v1(107.55,138.655) CN10.11@109.523,138.655 ; v1(109.548,88.655) CN16.30@114.4,88.655
  Signal Layer 1 w0.08: v1(71.675,123.85) 73.525,123.85 74.675,125 74.675,125.675 v2(74.75,125.75)
  Signal Layer 2 w0.09: v1(100.65,123.753) 100.65,133.986 100.904,134.24 v1(100.904,138.655) ; v1(107.55,138.655) 107.55,133 109.15,131.4 109.15,124.949 109.776,124.323 109.776,103.74 109.548,103.512 109.548,89.425 108.85,88.727 108.85,87.925 108.821,87.896 108.821,87.861 108.589,87.629 108.354,87.629 108,87.275 108,64.35 108.1,64.25 108.3,64.25 108.375,64.325 108.375,86.95 108.475,87.05 108.675,87.05 108.775,86.95 108.775,64.35 108.875,64.25 109.075,64.25 109.208,64.383 109.208,87.862 109.548,88.202 v1(109.548,88.655)
  Bottom Layer w0.1: v1(71.675,123.85) 72.025,123.85 72.125,123.75 72.912,123.75 73.262,124.1 81.991,124.1 82.758,123.333 89.058,123.333 89.478,123.753 v1(100.65,123.753)
DCMI_PIXCLK: CN16.33 R145.1 | length 120.2
  Top Layer w0.1: CN16.33@116.95,90.655 v1(119.634,90.655)
  Signal Layer 2 w0.09: v1(116.575,137.375) 116.042,136.842 116.042,124.337 117.859,122.52 117.859,120.825 116.092,119.058 116.092,105.183 119.634,101.641 119.634,97.791 119.138,97.295 119.138,93.129 119.634,92.633 119.634,91.366 121.575,89.425 121.575,74.175 121.5,74.1 121.25,74.1 121.125,74.225 121.125,89.25 121,89.375 120.8,89.375 120.675,89.25 120.675,74.2 120.575,74.1 120.342,74.1 120.242,74.2 120.242,89.262 119.634,89.87 v1(119.634,90.655)
  Bottom Layer w0.1: R145.1@115.05,137.375 v1(116.575,137.375)
EXT_RESET: CN4.5 U15.29 | length 116.3
  Top Layer w0.12: CN4.5@9.22,167.375 9.22,165.05 10.395,163.875 16.513,163.875 v1(17.613,162.775) ; v1(35.248,78.648) U15.29@35.248,79.75
  Signal Layer 2 w0.12: v1@17.625,162.763 17.625,160.464 17.111,159.95 17.111,156.206 17.325,155.992 17.325,153.44 17.325,137.42 18.845,135.9 19.88,135.9 20.43,135.35 20.43,120.37 22.125,118.675 22.125,109.988 19.025,106.888 19.025,87.6 18.57,87.145 18.57,85.755 19.825,84.5 v1(19.825,80.2)
  Bottom Layer w0.12: v1(19.825,80.2) 23.25,80.2 24.802,78.648 v1(35.248,78.648)
FMC_A22_LCD_RS: CN23.2 R198.1 | length 110.6
  Top Layer w0.1: v1(88.125,62.425) 105.255,62.425 CN23.2@106.5,61.18
  Signal Layer 2 w0.09: v1(69.025,95.65) 69.025,76.275 69.15,76.15 69.35,76.15 69.45,76.25 69.45,81.775 69.525,81.85 69.753,81.85 69.875,81.728 69.875,76.25 70,76.125 70.225,76.125 70.3,76.2 70.3,80.875 70.425,81 70.603,81 70.725,80.878 70.725,76.225 70.825,76.125 71.025,76.125 71.1,76.2 71.1,80.075 71.201,80.176 71.426,80.176 71.525,80.078 71.525,76.275 71.6,76.2 71.775,76.2 71.875,76.3 71.875,79.35 72,79.475 72.128,79.475 72.275,79.328 72.275,76.35 72.375,76.25 72.525,76.25 72.65,76.375 72.65,78.6 72.725,78.675 73.125,78.675 88.125,63.675 v1(88.125,62.425)
  Bottom Layer w0.1: R198.1@60.375,95.65 v1(69.025,95.65)
FMC_NBL0: R176.1 U12.A1 | length 32.8
  Top Layer w0.1: v1(75.4,87.45) U12.A1@75.4,88.946
  Signal Layer 2 w0.09: v1(74.5,104.8) 74.5,92.625 75.4,91.725 v1(75.4,87.45)
  Bottom Layer w0.1: R176.1@60.95,104.8 v1(74.5,104.8)
FMC_NBL1: R181.1 U12.B2 | length 31.9
  Top Layer w0.1: v1(75.775,88.45) 75.775,89.321 U12.B2@76.15,89.696
  Signal Layer 2 w0.09: v1(74.9,104.2) 74.9,92.825 75.775,91.95 v1(75.775,88.45)
  Bottom Layer w0.1: R181.1@60.95,103.375 60.95,103.575 61.575,104.2 v1(74.9,104.2)
FMC_NE1: R37.1 R202.1 U12.B5 | length 30.5
  Top Layer w0.1: v1(72.075,97.2) 74.975,97.2 75.55,96.625 R37.1@75.65,96.525 ; R37.1@75.85,96.525 R37.1@75.65,96.525 ; U12.B5@76.15,91.946 75.775,92.321 75.775,93.192 75.5,93.467 75.5,96.525 R37.1@75.65,96.525
  Bottom Layer w0.1: R202.1@51.409,95.346 56.796,95.346 57.666,96.216 64.566,96.216 65.55,97.2 v1(72.075,97.2)
FMC_NE4_LCD_CSn: CN23.1 R187.2 | length 77.1
  Top Layer w0.1: v1(88.625,61.18) CN23.1@103.96,61.18
  Signal Layer 2 w0.09: v1(69.475,100.125) 69.475,82.825 88.625,63.675 v1(88.625,61.18)
  Bottom Layer w0.1: R187.2@54.825,100.675 57.025,100.675 57.575,100.125 v1(69.475,100.125)
FMC_NOE: CN23.4 R216.1 U12.A2 | length 109.5
  Top Layer w0.1: v1(73.904,89.696) U12.A2@75.4,89.696 ; v1(90.075,59.875) 86,59.875 85.925,59.95 85.925,60.175 86.05,60.3 90.3,60.3 90.725,59.875 105.265,59.875 CN23.4@106.5,58.64
  Signal Layer 2 w0.09: v1(73.904,89.696) 73.904,80.371 90.075,64.2 v1(90.075,59.875)
  Bottom Layer w0.1: R216.1@51.409,91.071 51.409,91.284 52.05,91.925 57.375,91.925 57.575,91.725 57.575,91.525 57.5,91.45 52.55,91.45 52.325,91.225 52.325,91.071 52.471,90.925 57.525,90.925 57.675,90.775 57.675,90.625 57.525,90.475 52.4,90.475 52.3,90.375 52.3,90.05 52.45,89.9 60.615,89.9 60.826,90.111 70.999,90.111 71.398,89.713 73.887,89.713 v1(73.904,89.696)
FMC_NWE: CN23.3 R210.1 U12.G5 | length 112.6
  Top Layer w0.1: U12.G5@79.9,91.946 80.275,91.571 v1(81.146,91.571) ; v1(96.175,58.64) 96.173,58.642 86.683,58.642 86.5,58.825 86.5,59 86.675,59.175 96.525,59.175 97.06,58.64 CN23.3@103.96,58.64
  Signal Layer 2 w0.09: v1(71.225,92.615) v1(71.225,94.85) ; v1(81.146,91.571) 80.775,91.2 80.775,88.05 81.075,87.75 81.075,81.675 96.175,66.575 v1(96.175,58.64)
  Bottom Layer w0.1: R210.1@51.409,92.471 51.588,92.65 52.144,92.65 52.994,93.5 57.65,93.5 57.775,93.375 57.775,93.15 57.65,93.025 53.275,93.025 53.175,92.925 53.175,92.571 53.275,92.471 61.106,92.471 61.251,92.615 61.44,92.615 61.75,92.925 70.915,92.925 v1(71.225,92.615) ; v1(71.225,94.85) 74.125,94.85 76.7,92.275 80.442,92.275 v1(81.146,91.571)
